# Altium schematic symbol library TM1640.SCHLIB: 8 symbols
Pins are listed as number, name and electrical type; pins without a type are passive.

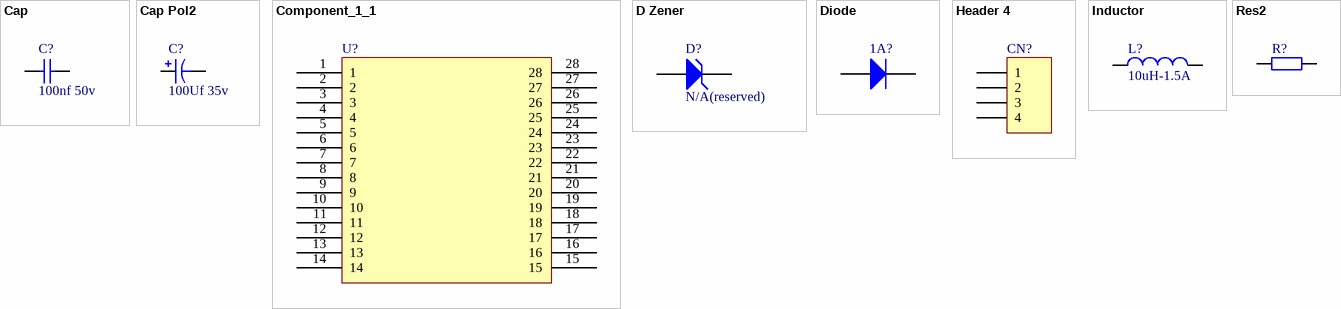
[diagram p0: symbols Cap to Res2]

## Cap
designator C?, comment 100nf 50v
Capacitor
simulation model CAP (Capacitor)
signal-integrity model Cap
footprint µç×èÕýÃæ
pins: 1, 2

## Cap Pol2
designator C?, comment 100Uf 35v
Polarized Capacitor (Axial); Value: 330Uf 35v
simulation model CAP (Capacitor)
signal-integrity model Cap Pol
footprint µç½âµçÈÝ47UF
pins: 1, 2
1 alternate drawing of the same symbol

## Component_1_1
designator U?, comment TM1640  (value not drawn)
footprint sop28
pins: 1, 2, 3, 4, 5, 6, 7, 8, 9, 10, 11, 12, 13, 14, 15, 16, 17, 18, 19, 20, 21, 22, 23, 24, 25, 26, 27, 28

## D Zener
designator D?, comment N/A(reserved)
Zener Diode
simulation model ZENER (Diode)
signal-integrity model D Zener
footprint SOD-323
pins: 1 A, 2 K

## Diode
designator 1A?  (value not drawn)
Default Diode
simulation model DIODE (Diode)
signal-integrity model Diode
footprint 0603
pins: 1 A, 2 K

## Header 4
designator CN?  (value not drawn)
Header, 4-Pin
signal-integrity model Connector
footprint 0.75(1-4)
pins: 1, 2, 3, 4

## Inductor
designator L?, comment 10uH-1.5A
Inductor; Code_IEC: 1005
simulation model INDUCTOR (Inductor)
signal-integrity model Inductor
footprint µç¸Ð404018
pins: 1, 2

## Res2
designator R?, comment 10k 5%  (value not drawn)
Resistor
simulation model RESISTOR (Resistor)
signal-integrity model Res
footprint µç×èÕýÃæ
pins: 1, 2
